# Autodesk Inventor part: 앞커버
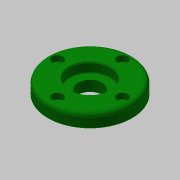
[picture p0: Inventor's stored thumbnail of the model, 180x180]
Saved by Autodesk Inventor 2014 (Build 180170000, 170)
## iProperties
Created: 2015-09
Part Number: 앞커버
Material: 알루미늄 6061
Document SubType Name: Modeling
Designer: mduedu
Density: 1 g/cm^3
Appearance: Dark Green
Author: mduedu
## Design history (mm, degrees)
sketch "스케치1"
  geometry: L1 (0, 7.5)-(0, -7.5); L2 (0, 7.5)-(31, 7.5); L3 (31, 7.5)-(31, -2.5); L4 (31, -2.5)-(17.5, -2.5); L5 (17.5, -2.5)-(17.5, -7.5); L6 (17.5, -7.5)-(0, -7.5); 2 further points
  constraints: 12 end point, 2 parallel, 2 perpendicular, 1 coincident, 1 horizontal, 1 midpoint, 1 vertical
  dimensions: "d0" = 15 distance of L1.start L1.end; "d1" = 62 diameter of L3 L1; "d2" = 35 diameter of L5 L1; "d3" = 10 distance of L2.end L3.end
revolve "회전1" sketch "스케치1" stored, may be unused: angle "d4" = 90 deg
hole "구멍1" diameter "d7" = 30; stored, may be unused: countersink angle "d11" = 90 deg, drill point angle "d13" = 0 deg; dims "d8" = 6, "d9" = 4, "d10" = 2, "d12" = 7.3, "d46" = 10, "d47" = 10
hole "구멍2" diameter "d16" = 18; stored, may be unused: countersink angle "d20" = 90 deg, drill point angle "d22" = 0 deg; dims "d14" = 10, "d15" = 10, "d17" = 6, "d18" = 4, "d19" = 2, "d21" = 7.3
fillet "모깎기2" dims "d48" = 3
chamfer "모따기2" distance "d26" = 0.7; stored, may be unused: second distance "d27" = 2, angle "d28" = 30 deg
fillet "모깎기1" dims "d29" = 0.3
sketch "스케치4" dims "d49" = 48
  geometry: 3 further points
  constraints: 2 vertical alignment, 1 coincident, 2 other
hole "구멍4" sketch "스케치4" at (0, 24) diameter "d50" = 4.5; stored, may be unused: countersink angle "d54" = 90 deg, drill point angle "d56" = 118 deg; dims "d51" = 6, "d52" = 8, "d53" = 4.4, "d55" = 8
chamfer "모따기3" distance "d43" = 1; stored, may be unused: second distance "d44" = 2, angle "d45" = 45 deg
node "솔리드1"
pattern_circular "원형 패턴1" dims angle "d58" = 360 deg
